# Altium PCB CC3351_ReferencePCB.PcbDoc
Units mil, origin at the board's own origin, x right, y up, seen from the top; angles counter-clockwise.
Board outline 433.07 x 433.07 mil, 4 copper layers (L01_TOP, L02_GND, L03_PWR, L04_BOTTOM), stack 29.496 mil thick; 15 components, 31 nets, 77 pads, 114 vias.
Unrouted connection lines stored in the file: 2.
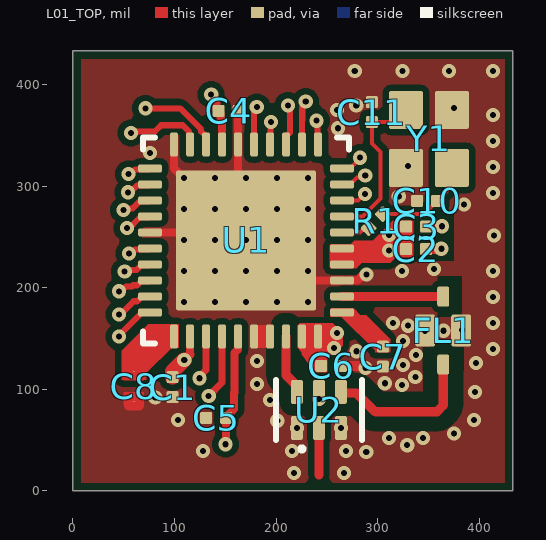
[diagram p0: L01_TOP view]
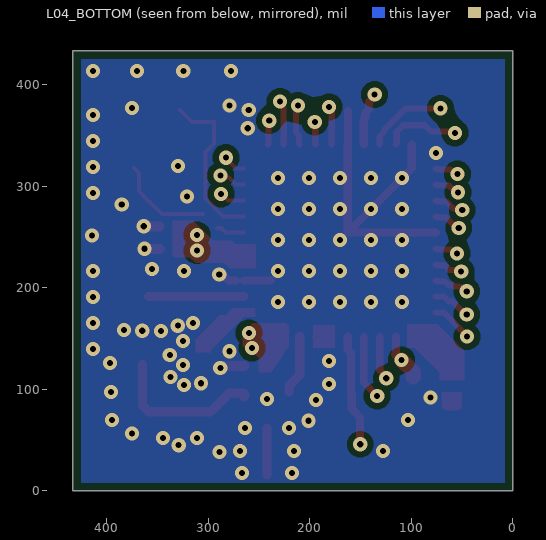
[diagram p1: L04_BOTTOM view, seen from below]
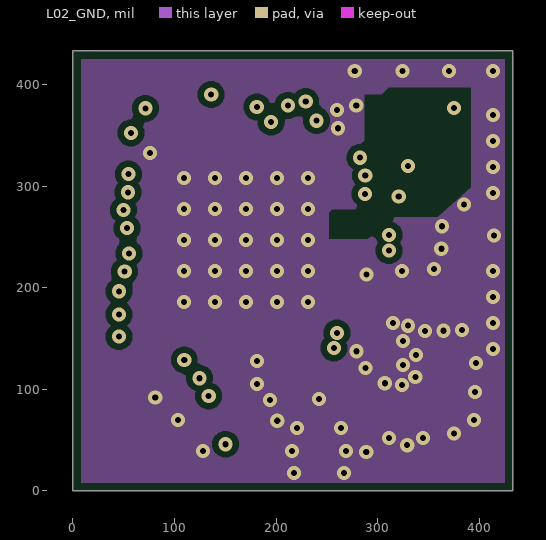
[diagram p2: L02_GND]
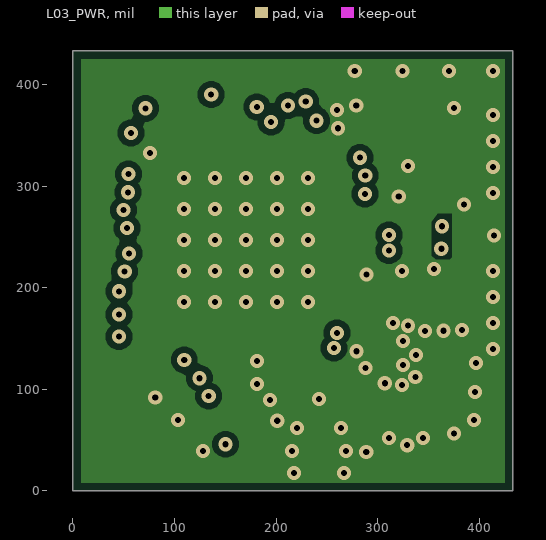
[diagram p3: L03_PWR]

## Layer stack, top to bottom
Top Solder: solder mask 1, Solder Resist, Dk 3.5
L01_TOP: signal copper 0.689
Dielectric1: prepreg 5.4819, IT-170GTTC, Dk 4
L02_GND: signal copper 1.2598
Dielectric 2: core 14.635, IT-170GTTC, Dk 4
L03_PWR: signal copper 1.2598
Dielectric 3: prepreg 5.4819, IT-170GTTC, Dk 4
L04_BOTTOM: signal copper 0.689
Bottom Solder: solder mask 1, Solder Resist, Dk 3.5

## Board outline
433.07,433.07 0,433.07 0,0 433.07,0

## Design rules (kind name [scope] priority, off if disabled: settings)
AcuteAngle [All] p1: minimum=4.50000000000000E+0001 checktracksonly=FALSE
AssemblyTestPointUsage [All] p1: valid=2
BoardOutlineClearance BoardOutlineClearance_MountingHoles [OnCopper and InComponentClass('Mounting Holes')] p1: gap=39.37 ignorepadtopadclearanceinfootprint=FALSE
BoardOutlineClearance BoardOutlineClearance_Poly [OnCopper and IsPoly] p2: gap=0 ignorepadtopadclearanceinfootprint=FALSE except(7.87: Poly-OutlineEdge)
BoardOutlineClearance [OnCopper and Not InComponentClass('Logo') and not InComponentClass('FiducialMark') and not InRegion(1000,500,4000,800) and not InPoly] p3: gap=9.84 ignorepadtopadclearanceinfootprint=FALSE
Clearance Clearance_RF [InNetClass('RF') vs InNet('GND')] p1: gap=6 ignorepadtopadclearanceinfootprint=TRUE except(7.87: Poly-Poly; 11: THPad-Poly Via-Poly; 11.25: SMDPad-Poly Fill-Poly; 15: Arc-Poly Track-Poly)
Clearance Clearance_Keepouts [((IsTrack Or IsArc) And Not InPoly) And IsFree and IsKeepOut vs ((IsTrack Or IsArc) And Not InPoly) And IsFree and IsKeepOut] p2: gap=0 ignorepadtopadclearanceinfootprint=FALSE
Clearance Clearance_Poly [InPolygon] p3: gap=6 ignorepadtopadclearanceinfootprint=TRUE except(5.5: Poly-Poly)
Clearance Clearance_FiducialMark [IsKeepOut and InComponentClass('FiducialMark') vs IsPad and InComponentClass('FiducialMark')] p4: gap=0 ignorepadtopadclearanceinfootprint=FALSE
Clearance [All] p5: gap=4 ignorepadtopadclearanceinfootprint=TRUE
ComponentClearance "Ignore Mod Component" [InComponent('CC1')] p1: gap=0 collisioncheckmode=3 verticalgap=0 showdistances=FALSE
ComponentClearance ComponentClearance_MountingHoles_FiducialMarks [InComponentClass('Mounting Holes') vs InComponentClass('FiducialMark')] p2: gap=50 collisioncheckmode=3 verticalgap=10 showdistances=FALSE
ComponentClearance ComponentClearance_Shunt [InComponentClass('Header') vs InComponentClass('Shunt')] p3: gap=0 collisioncheckmode=3 verticalgap=0 showdistances=FALSE
ComponentClearance ComponentClearance_Logo [InComponentClass('Logo')] p4: gap=30 collisioncheckmode=3 verticalgap=10 showdistances=FALSE
ComponentClearance ComponentClearance_ScrewToNut [(HasFootprint('NY PMS 440 0025 PH')) vs (HasFootprint('Keystone_1902C'))] p5: gap=5 collisioncheckmode=3 verticalgap=10 showdistances=FALSE
ComponentClearance ComponentClearance_MountingHoles [InComponentClass('Mounting Holes')] p6: gap=100 collisioncheckmode=3 verticalgap=100000 showdistances=FALSE
ComponentClearance ComponentClearance_SmallPassives [HasFootprint('0201*') or HasFootprint('0402*') or HasFootprint('0508') or HasFootprint('0603*') or HasFootprint('0612') or HasFootprint('0805*') or HasFootprint('0815*') or HasFootprint('0830*') or HasFootprint('1206*') or HasFootprint('1210*') or HasFootprint('1808*') or HasFootprint('1812*') or HasFootprint('1825*') or HasFootprint('2010*') or HasFootprint('2220*') or HasFootprint('2225*') or HasFootprint('2512*') or HasFootprint('2728*') or HasFootprint('3518*') vs HasFootprint('0201*') or HasFootprint('0402*') or HasFootprint('0508') or HasFootprint('0603*') or HasFootprint('0612') or HasFootprint('0805*') or HasFootprint('0815*') or HasFootprint('0830*') or HasFootprint('1206*') or HasFootprint('1210*') or HasFootprint('1808*') or HasFootprint('1812*') or HasFootprint('1825*') or HasFootprint('2010*') or HasFootprint('2220*') or HasFootprint('2225*') or HasFootprint('2512*') or HasFootprint('2728*') or HasFootprint('3518*')] p7: gap=8 collisioncheckmode=3 verticalgap=10 showdistances=FALSE
ComponentClearance ComponentClearance_THtoSMT [IsThruComponent vs IsSMTComponent] p8: gap=30 collisioncheckmode=3 verticalgap=30 showdistances=FALSE
ComponentClearance ComponentClearance_THtoTH [IsThruComponent vs IsThruComponent] p9: gap=20 collisioncheckmode=3 verticalgap=30 showdistances=FALSE
ComponentClearance [All] p10: gap=0 collisioncheckmode=3 verticalgap=10 showdistances=FALSE
DiffPairsRouting [All] p1: maxlimit=100 minlimit=10 mostfreqgap=10 toplayer_minwidth=15 toplayer_maxwidth=15 toplayer_prefwidth=15 midlayer1_minwidth=15 midlayer1_maxwidth=15 midlayer1_prefwidth=15 midlayer2_minwidth=15 midlayer2_maxwidth=15 midlayer2_prefwidth=15 bottomlayer_minwidth=15 bottomlayer_maxwidth=15 bottomlayer_prefwidth=15 maxuncoupledlength=1000
FabricationTestPointUsage TestPointUsage [All] p1: valid=2 allowmultiple=FALSE
FabricationTestpoint Testpoint [All] p1: side=3 testpointundercomponent=TRUE minsize=40 maxsize=100 preferedsize=60 minholesize=0 maxholesize=40 preferedholesize=32 testpointgrid=1 allowsidetop=TRUE allowsidebottom=TRUE usegrid=TRUE gridtolerance=0.01
FanoutControl Fanout_LCC [IsLCC] p1: bgadir=Out bgaviamode=Centered fanoutstyle=Auto fanoutdirection=Alternating viagrid=1 // Fanout_LCC (Default Rule)
FanoutControl Fanout_BGA [IsBGA] p2: bgadir=Out bgaviamode=Centered fanoutstyle=Auto fanoutdirection=Alternating viagrid=1 // Fanout_BGA (Default Rule)
FanoutControl Fanout_Default [All] p4: bgadir=Out bgaviamode=Centered fanoutstyle=Auto fanoutdirection=Alternating viagrid=1 // Fanout_Default (Default Rule)
FanoutControl Fanout_Small [(CompPinCount < 5)] p5: bgadir=Out bgaviamode=Centered fanoutstyle=Auto fanoutdirection=OutThenIn viagrid=1 // Fanout_Small (Default Rule)
HoleSize [All] p1: absolutevalues=TRUE maxlimit=251 minlimit=6 maxpercent=80.000 minpercent=20.000
HoleToHoleClearance [All] p1: gap=7 allowstackedmicrovias=TRUE
MinimumAnnularRing MinimumAnnularRing_ThermalPadVias [IsVia and InAnyComponent] p1: minimumring=3
MinimumAnnularRing [All] p2: minimumring=3
MinimumSolderMaskSliver MinimumSolderMaskSliver_Logo [InComponentClass('Logo') vs InComponentClass('Logo')] p1: minsoldermaskwidth=0.7
MinimumSolderMaskSliver [All] p2: minsoldermaskwidth=3.94
PlaneConnect [All] p1: planeconnectstyle=Direct reliefexpansion=10 reliefentries=4 reliefconductorwidth=10 reliefairgap=10
PolygonConnect [All] p1: connectstyle=Direct reliefconductorwidth=10 reliefentries=4 polygonreliefangle="90 Angle" airgapwidth=10
RoutingVias ThermalPadVias [IsVia and InAnyComponent] p1: holewidth=7.87 width=19.68 viastyle="Through Hole" minholewidth=6 minwidth=10 maxholewidth=12.99 maxwidth=23.62
RoutingVias [All] p2: holewidth=16 width=34 viastyle="Through Hole" minholewidth=6 minwidth=10 maxholewidth=40 maxwidth=65
SilkToBoardRegionClearance [Not ((IsComment or IsDesignator) And (Hide <> 'False')) and not InRegion(1000,500,4000,800)] p1:
SilkToSilkClearance SilkToSilkClearance_Pb-FreeLogo [(HasFootprint('Pb-Free_Overlay_Medium') OR HasFootprint('Pb-Free_Overlay_Small')) vs (HasFootprint('Pb-Free_Overlay_Medium') OR HasFootprint('Pb-Free_Overlay_Small'))] p1: silktosilkclearance=0
SilkToSilkClearance [All] p2: silktosilkclearance=3.94
SilkToSolderMaskClearance SilkToComponentPadClearance [(IsPad or IsFill or IsRegion) and InAnycomponent] p1: minsilkscreentomaskgap=5 clearancetoexposedcopper=TRUE
SilkToSolderMaskClearance "Silk to Solder Mask Opening" [All] p2: minsilkscreentomaskgap=3.94 clearancetoexposedcopper=FALSE
SolderMaskExpansion [All] p1: expansion=1.97 istentingtop=FALSE
UnRoutedNet [All] p1: checkbadconnections=TRUE
Width [All] p1: maxlimit=100 minlimit=4 preferedwidth=10 midlayer1_minwidth=6 midlayer2_minwidth=6 minimp=50.000000 maximp=50.000000 favimp=50.000000 checkconnectedcopper=TRUE
13 further rules are at their usual default settings.

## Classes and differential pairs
net class RF: NetFL1_3 RF_A

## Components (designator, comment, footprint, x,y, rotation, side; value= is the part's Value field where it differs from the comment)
C1 "GRM033C71A104KE14D" 0201#1 98.07,99.07 r270 top value=0.1uF
C2 "GRM033C71A104KE14D" 0201#1 340.78,238.05 r0 top value=0.1uF
C3 "GRM033C71A104KE14D" 0201#1 341,260.1 r0 top value=0.1uF
C4 "GRM033C71A104KE14D" 0201#2 150.07,374.07 r0 top value=0.1uF
C5 "GRM033C71A104KE14D" 0201#1 137.8,71.85 r180 top value=0.1uF
C6 "GRM033D70J105ME01D" FP-GRM033D70J105ME01D_0201-MFG#1 252.95,123.03 r180 top value=1µF
C7 "GRM033D70J105ME01D" FP-GRM033D70J105ME01D_0201-MFG#2 305.12,130.91 r90 top value=1µF
C8 "GRM155R70J105MA12D" 0402 60.07,94.07 r270 top value=1uF
C10 "GRM0335C1H6R8BA01D" 0201#1 345.47,285.43 r180 top value=6.8pF
C11 "GRM0335C1H6R8BA01D" 0201#1 294.29,375.98 r90 top value=6.8pF
FL1 "DEA162450BT-1295A1" FP-DEA162450BT-1295A1_SMT_FILTER_1MM60_0MM80-MFG 364.49,157.89 r270 top
R1 "RC0201FS-7D150RL" 0201#1 300.2,267.72 r45 top value=150
U1 "CC3351NG0ARSBR" RSB0040B-MFG 170.4,246.57 r180 top
U2 "DPX167125DT-8197B1" FP-DPX167125DT-8197B1_SMD6-MFG 242.13,79.72 r0 top
Y1 "TZ3877AAAO44" FP-TZ3877AAAO44_SMT4_2MM05_1MM65-MFG 350.39,346.46 r90 top

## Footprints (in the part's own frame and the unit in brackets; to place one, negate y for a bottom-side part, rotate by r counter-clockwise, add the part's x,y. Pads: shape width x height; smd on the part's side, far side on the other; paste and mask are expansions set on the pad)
0201#1 [mm] "Data from Kemet datasheet CC101_COM dated 7/28/11"
  rrect25% 0.3x0.3 smd mask+0.048: 1(-0.33,0) 2(0.17,0)
  body extent -0.31,-0.16 0.31,0.16, height 0.26
0201#2 [mm] "Data from Kemet datasheet CC101_COM dated 7/28/11"
  rrect25% 0.3x0.3 smd mask+0: 1(-0.17,0) 2(0.33,0)
  body extent -0.31,-0.16 0.31,0.16, height 0.26
0402 [mil] "0402 from SM-752 data"
  round 1 smd: 1(-23.62,0) 2(5.91,0)
  L01_TOP region: -14.76,9.84 -14.76,-9.84 -27.17,-9.84 -29.2,-9.44 -30.92,-8.29 -32.08,-6.56 -32.48,-4.53 -32.48,-4.53 -32.48,4.53 -32.08,6.56 -30.92,8.29 -29.2,9.44 -27.17,9.84 -27.17,9.84
  L01_TOP region: 14.76,-4.53 14.36,-6.56 13.21,-8.29 11.48,-9.44 9.45,-9.84 9.45,-9.84 -2.95,-9.84 -2.95,9.84 9.45,9.84 11.48,9.44 13.21,8.29 14.36,6.56 14.76,4.53 14.76,4.53
  body extent -22,-12 22,12, height 24
FP-DEA162450BT-1295A1_SMT_FILTER_1MM60_0MM80-MFG [mm]
  rrect33% 0.5x0.3 smd paste+0 mask+0.025: 1(-0.85,0) 3(0.85,0)
  rrect20% 0.8x0.5 smd paste+0 mask+0.025: 2(0,-0.45) 4(0,0.45)
  body extent -1.2,-0.8 1.2,0.8, height 0.25
FP-DPX167125DT-8197B1_SMD6-MFG [mm]
  rrect33% 0.3x0.6 smd paste+0 mask+0: 1(-0.55,-0.45) 2(0,-0.45) 3(0.55,-0.45) 4(0.55,0.45) 5(0,0.45) 6(-0.55,0.45)
  silkscreen extent -1.07,-1.03 1.07,0.75, body extent -0.95,-0.85 0.95,0.85, height 0.25
FP-GRM033D70J105ME01D_0201-MFG#1 [mm]
  rrect33% 0.3x0.3 smd paste+0 mask+0: 1(-0.282,0) 2(0.218,0)
  body extent -0.53,-0.3 0.53,0.3, height 0.25
FP-GRM033D70J105ME01D_0201-MFG#2 [mm]
  rrect33% 0.3x0.3 smd paste+0 mask+0: 1(-0.218,0) 2(0.282,0)
  body extent -0.53,-0.3 0.53,0.3, height 0.25
FP-TZ3877AAAO44_SMT4_2MM05_1MM65-MFG [mm]
  rrect12% 0.95x0.85 smd paste+0 mask+0: 1(-0.725,-0.575) 2(0.725,-0.575) 3(0.725,0.575) 4(-0.725,0.575)
  body extent -1.3,-1.1 1.3,1.1, height 0.25
RSB0040B-MFG [mm]
  rrect50% 0.6x0.2 smd paste+0 mask+0: 1(-2.4,1.8) 3(-2.4,1) 4(-2.4,0.6) 5(-2.4,0.2) 6(-2.4,-0.2) 7(-2.4,-0.6) 8(-2.4,-1) 9(-2.4,-1.4) 10(-2.4,-1.8) 21(2.4,-1.8) 22(2.4,-1.4) 23(2.4,-1) 24(2.4,-0.6) 25(2.4,-0.2) 26(2.4,0.2) 27(2.4,0.6) 28(2.4,1) 29(2.4,1.4) 30(2.4,1.8)
  rrect50% 0.6x0.2 smd: 2(-2.4,1.4)
  rrect50% 0.2x0.6 smd paste+0 mask+0: 11(-1.8,-2.4) 12(-1.4,-2.4) 13(-1,-2.4) 14(-0.6,-2.4) 15(-0.2,-2.4) 16(0.2,-2.4) 17(0.6,-2.4) 18(1,-2.4) 19(1.4,-2.4) 20(1.8,-2.4) 31(1.8,2.4) 32(1.4,2.4) 33(1,2.4) 34(0.6,2.4) 35(0.2,2.4) 36(-0.2,2.4) 37(-0.6,2.4) 39(-1.4,2.4) 40(-1.8,2.4)
  rrect50% 0.2x0.6 smd: 38(-1,2.4)
  rrect3% 3.5x3.5 smd paste-1000 mask+0: 41(0,0)
  silkscreen extent -2.58,-2.58 2.58,2.58, body extent -2.8,-2.8 2.8,2.8, height 0.25

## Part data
C1 C2 C3 C4 C5: library part CMP-0064969-1, "CAP, CERM, 0.1 uF, 10 V,+/- 10%, X7S, 0201", Cap_Case=0201, Manufacturer=MuRata, Supplier Part Number 1=490-14450-1-ND, Value1=Unknown, Value2=10V, ValueDisplayed=0.1uF
C6 C7: library part CMP-0095016-1, "Chip Multilayer Ceramic Capacitors for General Purpose, 0201, 1.0uF, X7T, +22%/-33%, 20%, 6.3V", Manufacturer=Murata, Operating Temperature Range="-55°C to +125°C", TempCo=+22%/-33%, Tolerance_%=20%, ValueDisplayed=1.0uF
C8: library part CMP-0006624-2, "CAP, CERM, 1 uF, 6.3 V, +/- 20%, X7R, 0402", Cap_Case=0402, Manufacturer=MuRata, Supplier Part Number 1=490-9665-1-ND, TempCo=X7R, Tolerance_%=20%, Value1=Unknown, Value2=6.3V, ValueDisplayed=1uF
C10 C11: library part CMP-0009669-4, "CAP, CERM, 6.8 pF, 50 V, +/- 2%, C0G/NP0, 0201", Cap_Case=0201, Manufacturer=MuRata, Supplier Part Number 1=GRM0335C1H6R8BA01D-ND, TempCo=C0G/NP0, Tolerance_%=2%, Value1=Unknown, Value2=50V, ValueDisplayed=6.8pF
FL1: library part CMP-0091509-1, "2.45GHz Center Frequency Band Pass RF Filter (Radio Frequency) 100MHz Bandwidth 1.8dB 0603 (1608 Metric), 3 PC Pad", Digikey Part Number=445-175610-1-ND, Frequency_Fixed=2.45GHz, Manufacturer=TDK, Mouser Part Number=810-DEA162450BT1295A, Operating Temperature Range="-40°C to +85°C"
R1: library part CMP-0028078-1, "RES, 150, 1%, 0.05 W, 0201", Manufacturer="Yageo America", Power_W=50mW, Supplier Part Number 1=603-RC0201FS-7D150RL, TempCo="200 ppm/C", Tolerance_%=1%, Value2=0.05W, Value_Code=150R, ValueDisplayed=150
U1: library part CMP-0094602-1, Manufacturer="Texas Instruments", Operating Temperature Range=to, Part Number=CC3301NG0ARSBR
U2: library part CMP-0091972-1, "Multilayer Diplexer For 2.4-2.5GHz W-LAN & Bluetooth / 5-7GHz W-LAN", Manufacturer=TDK, Operating Temperature Range="-40°C to +85°C"
Y1: library part CMP-0094297-1, "Crystal Unit SMD 2.0x1.6 40.0MHz", Frequency Stability=-16/+18ppm, Frequency Tolerance=5ppm, Frequency_Fixed=40MHz, Load Capacitance=7pF, Manufacturer="TAI-SAW TECHNOLOGY", Operating Temperature Range="-40°C to +105°C"

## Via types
v1: diameter 14, hole 6, L01_TOP to L04_BOTTOM, tented both sides, 78 vias
v2: diameter 14, hole 6, L01_TOP to L04_BOTTOM, 34 vias
v3: diameter 14, hole 6, L01_TOP to L04_BOTTOM, tented top, 2 vias

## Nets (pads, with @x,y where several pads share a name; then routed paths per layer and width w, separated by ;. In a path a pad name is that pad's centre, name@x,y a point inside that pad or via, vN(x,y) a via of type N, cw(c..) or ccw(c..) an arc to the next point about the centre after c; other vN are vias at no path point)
1V8: C1.1 C2.1 C3.1 C4.1 C5.1 U1.4 U1.5 U1.17 U1.32 U1.35 | length 215.9
  L01_TOP w7.8: 115.28,134.45 U1.32
  L01_TOP w8: v1@137.08,389.06 ccw(c136.07,389.06) v1(136.07,390.07) 136.07,388.45 141.47,383.05 141.47,375.98 C4.1 145.28,372.17 145.28,366.87 146.78,365.37 U1.17 ; v1(150.26,45.9) 150.52,46.17 150.52,71.59 C5.1 ; C5.1@153.64,75.64 158.57,80.57 158.57,96.25 159.22,96.9 159.22,135.99 162.53,139.3 U1.35
  L01_TOP w9: 104.42,123.59 115.28,134.45
  L01_TOP w15: C1.1 98.07,117.45 v2(109.54,128.92)
  other v2: 311.02,236.59 311.02,251.97
3V3: C6.2 U1.39 U1.40
  other v2: 256.89,140.75 259.84,155.51
ANT_SEL: U1.15 | length 38.1
  L01_TOP w6: U1.15 178.28,373.11 181,375.84 v2(181,378)
COEX_GRA: U1.10 | length 22.4
  L01_TOP w4: U1.10 272.77,317.44 282.48,327.15 v2(282.48,327.98)
COEX_PRI: U1.9 | length 26.5
  L01_TOP w4: U1.9 272.77,301.69 279.67,308.6 285.83,308.6 v2(287.74,310.51)
COEX_REQ: U1.8 | length 25.2
  L01_TOP w4: U1.8 280.44,285.94 286.82,292.32 v2(287.4,292.32)
DIG_LDO_OUT: C8.1 U1.31
GND: C1.2 C2.2 C3.2 C4.2 C5.2 C6.1 C7.1 C8.2 C10.2 C11.2 FL1.2 FL1.4 U1.3 U1.16 U1.20 U1.25 U1.36 U1.37 U1.41 U2.1 U2.3 U2.5 Y1.2 Y1.4 | length 420.9
  L01_TOP w7: U1.37@193.59,152.52 U1.37
  L01_TOP w8: U1.25 U1.41@162.53,254.45 ; U1.20 99.54,317.44 U1.41@162.53,254.45 ; C4.2@162.47,373.91 162.47,341.12 U1.16 U1.41@162.53,254.45 ; U1.41@238.07,207.07 238.2,207.2 U1.3 ; U1.3@272.7,207.26 279.92,207.26 284.51,211.85 286.23,211.85 287.38,213 v1(289,213)
  L01_TOP w10: C6.1 C6.1@264.96,123.03 ; C6.1@264.98,123.02 284.9,123.02 286.92,121 v1(288,121) ; C2.2 347.6,238.18 362.51,238.18 v2(362.64,238.31) ; C3.2 347.91,260.32 363.14,260.32 v2(363.36,260.55)
  other v1: 217.52,17.72 266.73,17.72 288.75,38.39 127.95,39.37 215.55,39.37 268.7,39.37 329,45 375,56.6 220.47,62.01 263.78,62.01 201.07,69.07 394.68,69.88 193.9,89.57 242.13,90.55 81.07,92.07 395.67,97.44 323.82,104.33 181.1,105.31 307,106 337,112 324.8,124.02 396.65,125.98 181.1,127.81 337.7,133.86 278.99,137.44 413.39,139.76 324.8,147.64 346.46,157.48 364.8,157.64 382.87,158.46 329.8,162.64 314.96,165.35 413.39,165.35 109.25,186.02 139.76,186.02 170.28,186.02 200.79,186.02 231.3,186.02 413.39,190.94 109.25,216.54 139.76,216.54 170.28,216.54 200.79,216.54 231.3,216.54 323.82,216.54 413.39,216.54 355.31,218.5 109.25,247.05 139.76,247.05 170.28,247.05 200.79,247.05 231.3,247.05 414.39,251.31 109.25,277.56 139.76,277.56 170.28,277.56 200.79,277.56 231.3,277.56 385,282 320.72,289.88 413.39,293.31 109.25,308.07 139.76,308.07 170.28,308.07 200.79,308.07 231.3,308.07 413.39,318.9 329.72,319.88 413.39,344.49 375,376.97 277.39,413.31 324.39,413.31 370.08,413.39
  other v2: 311.02,52.07 344.49,52.07 103.35,69.88 75.79,332.68 261,357 260,375 278.9,379.44
  other v3: 413.39,370.08 413.39,413.39
HFXT_M: C11.1 U1.7 Y1.3 | length 162.4
  L01_TOP w4: U1.7 285.25,270.19 302.78,287.73 302.78,333.51 294.29,342 C11.1 315.75,362.99 Y1.3
HFXT_P: R1.1 U1.6 | length 27.8
  L01_TOP w4: U1.6 282.7,254.45 286.79,258.53 R1.1
HOST_IRQ_BLE: U1.30 | length 41.1
  L01_TOP w6: v2(45.27,151.9) 45.27,152.93 68.04,175.71 U1.30
HOST_IRQ_WL: U1.29 | length 37.9
  L01_TOP w6: v2(45.45,173.52) 46.58,173.52 59.7,186.64 63.23,186.64 68.04,191.45 U1.29
LOGGER: U1.28 | length 34.9
  L01_TOP w6: v2(45.45,196.43) 47.61,196.43 52.49,201.31 58.03,201.31 59.11,202.39 63.23,202.39 67.1,206.26 74.98,206.26 U1.28
NetC10_1: C10.1 R1.2 Y1.1 | length 97.4
  L01_TOP w4: R1.2 345.48,272.45 C10.1 368.03,295 368.03,312.91 Y1.1
NetFL1_3: FL1.3 U2.4 | length 153.9
  L01_TOP w9.15: U2.4@265.11,92.48 263.78,93.81 263.78,95.11 265.11,96.44 278.9,96.44 297.15,78.19 ; 298,78 358.3,78 364.49,84.19 FL1.3
PA_LDO_OUT: C7.2 U1.1
RESET: U1.33 | length 43.8
  L01_TOP w7: v2(124.7,110.87) 124.7,112.76 131.03,119.1 U1.33
RF_A: U1.38 U2.6 | length 59.1
  L01_TOP w9.15: U1.38 209.77,114.05 220.47,103.35 U2.6
SDIO_CLK: U1.19 | length 75.9
  L01_TOP w6: v1(57.09,352.36) 58.62,353.89 80.79,353.89 86.77,359.87 108.1,359.87 114.35,353.63 114.35,342 U1.19
SDIO_CMD: U1.18 | length 80.3
  L01_TOP w6: v2(71.32,376.57) 105.54,376.57 126.22,355.89 126.22,353.74 131.03,348.93 U1.18
SDIO_D0: U1.24 | length 27.4
  L01_TOP w6: v2(53.31,258.73) 55.48,258.73 66,269.26 74.98,269.26 U1.24
SDIO_D1: U1.23 | length 30
  L01_TOP w6: v2(49.85,276.39) 51.38,277.92 58.61,277.92 65.69,285 74.98,285 U1.23
SDIO_D2: U1.22 | length 25
  L01_TOP w6: v2(54.13,293.88) 56.3,293.88 63.18,300.75 74.98,300.75 U1.22
SDIO_D3: U1.21 | length 23.6
  L01_TOP w6: v2(54.66,311.87) 56.83,311.87 61.46,316.5 74.98,316.5 U1.21
SLOW_CLOCK_IN: U1.34 | length 64
  L01_TOP w7: v2(133.62,93.54) 146.78,106.7 U1.34
SWCLK: U1.26 | length 22.9
  L01_TOP w6: v2(55.1,233.73) 57.27,233.73 61.3,237.76 74.98,237.76 U1.26
SWDIO: U1.27 | length 27.8
  L01_TOP w6: v2(50.92,216.08) 52.45,217.61 62.7,217.61 67.1,222.01 74.98,222.01 U1.27
UART_CTS: U1.12 | length 43.7
  L01_TOP w6: U1.12 225.52,364.22 225.75,364.45 225.75,377.61 229.2,381.06 v2(229.2,383.22)
UART_RTS: U1.11 | length 23.9
  L01_TOP w6: v2(239.82,364.4) 240.55,363.68 240.55,341.78 U1.11
UART_RX: U1.13 | length 40.7
  L01_TOP w6: U1.13 210.71,342 210.71,349.87 213.47,352.63 213.47,375.41 211.6,377.28 v2(211.6,379.44)
UART_TX: U1.14 | length 22.3
  L01_TOP w6: U1.14 194.51,341.55 194.51,362.51 v2(195,363)
pads on no net: FL1.1 U1.2 U2.2
copper on no net: | length 139.8
  L01_TOP w9.15: 242.13,16 242.13,62.01 ; 264.89,191.45 358.72,191.45

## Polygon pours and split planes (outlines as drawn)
GND on L03_PWR "L03_PWR_GND_P009" (solid, remove dead copper, pour order 9): 433.07,0 433.07,433.07 0,433.07 0,0
GND on L02_GND "L02_GND_GND_P001" (solid, remove dead copper, pour order 1): 433.07,433.07 0,433.07 0,0 433.07,0
GND on L01_TOP "L01_TOP_GND_P003" (solid, remove dead copper, pour order 3): 433.07,433.07 433.07,0 0,0 0,433.07
GND on L04_BOTTOM "L04_BOTTOM_GND_P007" (solid, remove dead copper, pour order 7): 433.07,0 433.07,433.07 0,433.07 0,0

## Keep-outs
Keep-Out Layer:
  text ".Layer_Name" at 611.35,-825.25 h60

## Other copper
L01_TOP:
  rectangle net GND: 175.2,140.75 196.85,163.39
  pour cut-out: 358.72,211.99 358.72,170.82 382.99,170.82 382.99,211.99
  pour cut-out: 344,117.86 385.17,117.86 385.17,142.14 344,142.14
  region net 3V3: 256.89,133.86 253.37,133.86 250.35,130.84 250.35,116.93 237.79,116.85 225.35,134.58 225.35,136.59 220.65,141.29 220.65,162.44 223.26,165.05 255.89,165.05 265.75,155.19 265.75,142.72
  region net 1V8: 253.9,219.07 252.9,220.07 252.9,241.57 253.9,242.57 273.4,242.57 276.9,246.07 295.14,246.07 314.81,265.75 334.9,265.75 334.9,231.57 333.4,230.07 317.9,230.07 312.4,224.57 284.4,224.57 278.9,219.07
  region net PA_LDO_OUT: 276.4,179.57 254.27,179.57 253.4,178.71 253.4,171.41 264.27,171.41 297.4,138.28 297.4,136.42 312.26,136.42 312.4,136.57 312.4,149.45 288.75,173.1 282.88,173.1
  pour cut-out: 342.52,226.38 342.52,272.64 375,272.64 375,226.38
  region net DIG_LDO_OUT: 104.07,141.07 104.07,144.68 104.07,164.07 74.07,164.07 48.07,138.07 48.07,109.25 72.07,109.25 72.07,116.07 97.07,141.07
  text ".Layer_Name" at 611.35,-825.25 h60
L02_GND:
  pour cut-out: 391.73,396.65 391.73,298.75 358.92,269.88 312.2,269.88 290.35,248.03 252.23,248.03 252.23,273.71 255.09,276.57 284.92,276.57 298.02,289.68 298.02,330.91 287.4,341.54 287.4,389.76 303.96,389.76 310.85,396.66
L03_PWR:
  pour cut-out: 353.18,265.05 359.15,272.64 373,272.63 373,229.83 371.03,227.86 356.88,227.86 353.18,231.55
L04_BOTTOM:
  text ".Layer_Name" at 611.35,-825.25 h60

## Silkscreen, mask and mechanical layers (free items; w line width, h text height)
Top Overlay:
  text ".Layer_Name" at 611.35,-825.25 h60
Bottom Overlay:
  text ".Layer_Name" at 611.35,-825.25 h60
Top Paste:
  region: 425.04,8.03 425.04,236 401.42,236 401.42,8.03
  region: 223,31.65 8.03,31.65 8.03,8.03 223,8.03
  region: 425.04,31.68 261,31.68 261,8.03 425.04,8.03
  region: 31.65,8.03 31.65,147.64 8.03,147.64 8.03,8.03
  region: 31.65,175.2 31.65,425.04 8.03,425.04 8.03,175.2
  region: 425.04,425.04 143.58,425.04 143.58,401.42 425.04,401.42
  region: 112.2,425.04 8.03,425.04 8.03,401.42 112.2,401.42
  region: 425.04,266.58 425.04,425.04 401.42,425.04 401.42,266.58
  text ".Layer_Name" at 611.35,-825.25 h60
Bottom Paste:
  text ".Layer_Name" at 611.35,-825.25 h60
Top Solder:
  region: 425.04,8.03 425.04,236 401.42,236 401.42,8.03
  region: 425.04,266.58 425.04,425.04 401.42,425.04 401.42,266.58
  region: 31.65,8.03 31.65,147.64 8.03,147.64 8.03,8.03
  region: 112.2,425.04 8.03,425.04 8.03,401.42 112.2,401.42
  region: 425.04,31.65 261,31.65 261,8.03 425.04,8.03
  region: 223,31.65 8.03,31.65 8.03,8.03 223,8.03
  region: 425.04,425.04 143.58,425.04 143.58,401.42 425.04,401.42
  region: 31.65,175.04 31.65,425.04 8.03,425.04 8.03,175.04
  text ".Layer_Name" at 611.35,-825.25 h60
  text ".Layer_Name" at 611.35,-825.25 h60
Bottom Solder:
  text ".Layer_Name" at 611.35,-825.25 h60
Drill Guide:
  text ".Layer_Name" at 611.35,-825.25 h60
M1 Board Outline:
  the board outline again, w10
  text ".Layer_Name" at 611.35,-825.25 h60
M2 Board Dimensions:
  rectangle: 34.35,-241.76 159.35,-116.76
  rectangle: 159.35,-366.76 534.35,-241.76
  lines w7: 34.35,-241.76 1034.35,-241.76 ; 159.35,-366.76 159.35,-116.76 ; 284.35,-366.76 284.35,-116.76 ; 534.35,-366.76 534.35,-116.76 ; 784.35,-366.76 784.35,-116.76 ; 34.35,-366.76 1034.35,-366.76 1034.35,-116.76 34.35,-116.76 34.35,-366.76
  text ".Layer_Name" at 611.35,-825.25 h60
M3 3D STEP Top:
  text ".Layer_Name" at 611.35,-825.25 h60
M4 3D STEP Bottom:
  text ".Layer_Name" at 611.35,-825.25 h60
M5 Assembly Top:
  lines w10: -257.65,-896.93 6342.35,-896.93 ; -257.65,-693.59 6344.35,-693.59 ; -257.65,-490.26 -257.65,-1100.26 3747.35,-1100.26 6344.35,-1100.26 6344.35,-490.26 -257.15,-490.26 -257.15,-1100.26 1318.35,-1100.26 ; 2207.35,-1100.26 2207.35,-490.26 ; 3474.35,-693.59 3474.35,-490.26 ; 4314.35,-693.59 4314.35,-490.26 ; 4936.35,-1106.76 4936.35,-903.93
  text "COMPONENTS MARKED 'DNP' SHOULD NOT BE POPULATED." at 1187.85,-285.26 h60
  text "ASSEMBLY VARIANT:" at 1187.35,-400.76 h60
  text ".VariantName" at 2223.35,-400.76 h60
  text "PCB VIEWED FROM TOP SIDE" at -194.15,-622.43 h60
  text "BOARD #:" at 2282.35,-622.43 h60
  text ".PRJ_Number" at 2827.85,-622.43 h60
  text "REV:" at 3672.35,-622.43 h60
  text ".PCB_Rev" at 3963.85,-622.43 h60
  text "SVN REV:" at 4510.35,-622.43 h60
  text ".VersionControl_RevNumber" at 5016.35,-622.43 h60
  text "TID #:" at 2282.35,-825.76 h60
  text ".TID" at 2827.85,-825.76 h60
  text "PLOT NAME =" at -194.15,-1031.09 h60
  text ".plot_File_Name" at 611.35,-1031.09 h60
  text "GENERATED    :" at 2284.35,-1031.09 h60
  text ".Print_Date" at 3153.85,-1031.09 h60
  text ".Print_Time" at 3882.85,-1031.09 h60
  text "TEXAS INSTRUMENTS" at 5147.35,-1031.09 h60
M6 Assembly Bottom:
  lines w10: -258.15,-694.09 6343.85,-694.09 ; -256.15,-897.43 6343.85,-897.43 ; 1149.85,-1107.26 1149.85,-904.43 ; 1771.85,-694.09 1771.85,-490.76 ; 2611.85,-694.09 2611.85,-490.76 ; 3878.85,-1100.76 3878.85,-490.76 ; 4767.85,-1100.76 6343.35,-1100.76 6343.35,-490.76 -258.15,-490.76 -258.15,-1100.76 2338.85,-1100.76 6343.85,-1100.76 6343.85,-490.76
  text "COMPONENTS MARKED 'DNP' SHOULD NOT BE POPULATED." at 6136.35,-284.76 h60
  text ".VariantName" at 5092.35,-400.76 h60
  text "ASSEMBLY VARIANT:" at 6131.35,-400.76 h60
  text ".VersionControl_RevNumber" at 1069.85,-622.93 h60
  text "SVN REV:" at 1575.85,-622.93 h60
  text ".PCB_Rev" at 2122.35,-622.93 h60
  text "REV:" at 2413.85,-622.93 h60
  text ".PRJ_Number" at 3258.35,-622.93 h60
  text "BOARD #:" at 3803.85,-622.93 h60
  text "PCB VIEWED FROM BOTTOM SIDE" at 6280.35,-622.93 h60
  text ".TID" at 3258.35,-826.26 h60
  text "TID #:" at 3803.85,-826.26 h60
  text "TEXAS INSTRUMENTS" at 938.85,-1031.59 h60
  text ".Print_Time" at 2203.35,-1031.59 h60
  text ".Print_Date" at 2932.35,-1031.59 h60
  text "GENERATED    :" at 3801.85,-1031.59 h60
  text ".plot_File_Name" at 5474.85,-1031.59 h60
  text "PLOT NAME =" at 6280.35,-1031.59 h60
M9 Title Sheet:
  drawing of 57 lines, arcs and shapes, not listed
  text "1" at 774.18,8069.74 h70
  text "2" at 3269.85,8069.74 h70
  text "3" at 5759.19,8069.74 h70
  text "4" at 8265.86,8069.74 h70
  text "5" at 10764.85,8069.74 h70
  text "6" at 13269.85,8069.74 h70
  text "A" at -382.15,6926.74 h70
  text "A" at 14417.85,6926.74 h70
  text "B" at -382.15,4546.74 h70
  text "B" at 14417.85,4546.74 h70
  text "C" at -382.15,2171.74 h70
  text "C" at 14417.85,2171.74 h70
  text "PROJECT TITLE:" at 11377.85,310.74 h45
  text ".PRJ_Title" at 11427.85,177.41 h70
  text "DESIGNED FOR:" at 11377.85,9.74 h45
  text ".PRJ_Customer" at 11427.85,-130.26 h70
  text "D" at -382.15,-198.26 h70
  text "D" at 14417.85,-198.26 h70
  text "FILE NAME:" at 11377.85,-290.26 h45
  text ".PCB_File_Name_No_Path" at 11427.85,-410.26 h70
  text "Texas Instruments (TI) and/or its licensors do not warrant the accuracy or completeness of this specification" at 6408.35,-572.1 h45
  text "ENGINEER:" at 11377.85,-580.26 h45
  text "LAYOUT BY:" at 12882.85,-580.26 h45
  text "or any information contained therein. TI and/or its licensors do not warrant that this design will meet" at 6363.36,-684.76 h45
  text ".PRJ_Engineer" at 11427.85,-735.25 h70
  text ".PCB_Layout" at 12933.35,-735.25 h70
  text "the specifications, will be suitable for your application or fit for any particular purpose, or will operate in" at 6363.36,-797.43 h45
  text ".Layer_Name" at 611.35,-825.25 h60
  text "ALTIUM DESIGNER VERSION:" at 12882.85,-890.26 h45
  text "an implementation. TI and/or its licensors do not warrant that the design is production worthy. You should" at 6363.36,-910.09 h45
  text "completely validate and test your design implementation to confirm the system functionality for your application." at 6408.35,-1022.76 h45
  text ".print_Scale" at 11427.85,-1023.59 h70
  text ".Application_BuildNumber" at 12933.35,-1023.59 h70
  text "1" at 774.18,-1230.26 h70
  text "2" at 3269.85,-1230.26 h70
  text "3" at 5759.19,-1230.26 h70
  text "4" at 8265.86,-1230.26 h70
  text "5" at 10764.85,-1230.26 h70
  text "6" at 13269.85,-1230.26 h70
M10 Fab Notes:
  drawing of 195 lines, arcs and shapes, not listed
  text "DESIGN INFORMATION" at 12416.37,6389.42 h60
  text "MIN. TRACK WIDTH:" at 11771.81,6257.29 h60
  text "4" at 12868.05,6257.29 h60
  text "MIL" at 13022.81,6257.29 h60
  text "4" at 12868.06,6146.89 h60
  text "MIN. CLEARANCE:" at 11771.81,6133.16 h60
  text "MIL" at 13022.81,6133.16 h60
  text "MIN. VIA PAD SIZE:" at 11771.81,6009.04 h60
  text "10" at 12838.06,6009.04 h60
  text "MIL" at 13022.81,6009.04 h60
  text "0.05mm (2MIL)" at 12466.81,5879.14 h60
  text "MINIMUM ANNULAR RING" at 11442.58,5870.92 h60
  text "EXTERNAL" at 13174.81,5870.92 h60
  text "PER" at 11642.58,5760.79 h60
  text "IPC-D-275 CLASS 2 LEVEL C" at 11862.58,5760.79 h60
  text "MIL, HOLES" at 13350.81,5660.31 h60
  text "+/-" at 12958.35,5651.72 h60
  text "+/-" at 13812.35,5651.72 h60
  text "REGISTRATION TOLERANCES:" at 11442.58,5650.66 h60
  text "METAL" at 12642.35,5650.66 h60
  text "5" at 13218.55,5650.66 h60
  text "3" at 14051.55,5650.66 h60
  text "MIL" at 14167.81,5650.66 h60
  text "HOLE SIZE TOLERANCE (UNLESS OTHERWISE SPECIFIED):" at 11442.58,5552.34 h60
  text "+/-" at 13812.35,5549.47 h60
  text "3" at 14051.55,5548.41 h60
  text "MIL" at 14167.81,5548.41 h60
  text "MATERIAL:" at 11367.81,5410.76 h60
  text "FR-4 High Tg" at 12354.25,5282.24 h60
  text "X" at 13095.43,5275.83 h60
  text "IT-170GTTC" at 13704.68,5273.86 h39.37
  text "FR-408" at 11788.81,5269.73 h60
  text "OTHER" at 13276.81,5269.73 h60
  text "0.8mm" at 13758.81,5130.16 h39.37
  text "62 MIL (1.6mm) +/-10%" at 12108.91,5126.7 h60
  text "X" at 13268.66,5126.23 h60
  text "THICKNESS:" at 11442.58,5118.48 h60
  text "OTHER" at 13393.81,5118.48 h60
  text "TOLERANCE:" at 11442.58,4980.16 h60
  text "X" at 12290.81,4980.16 h60
  text "ANSI IPC-6012 TYPE 3 CLASS 2" at 12468.82,4980.16 h60
  text "OTHER +/-" at 12468.81,4835.97 h60
  text "BOW & TWIST:" at 11442.58,4690.79 h60
  text "X" at 12290.81,4690.79 h60
  text "ANSI IPC-6012 TYPE 3 CLASS 2" at 12468.82,4690.79 h60
  text "OTHER +/-" at 12468.81,4544.09 h60
  text "DRILLING:" at 11367.81,4413.47 h60
  text "NC_DRILL FILES" at 13128.81,4308.28 h60
  text "REFERENCE:" at 11442.58,4304.34 h60
  text "X" at 12099.81,4304.25 h60
  text "AS SHOWN" at 12277.81,4304.34 h60
  text "X" at 13000.81,4304.34 h60
  text "OTHER" at 13426.81,4162.09 h60
  text "PTH COPPER THICKNESS:" at 11442.25,4158.56 h60
  text "X" at 12581.49,4158.56 h60
  text "20-30 um" at 12709.48,4158.56 h60
  text "BOARD FINISH:" at 11367.81,4010.97 h60
  text "SILKSCREEN:" at 11523.03,3900.84 h60
  text "X" at 12480.81,3900.84 h60
  text "TOP" at 12597.81,3900.84 h60
  text "X" at 12990.81,3900.84 h60
  text "BOTTOM" at 13108.81,3900.84 h60
  text "SILKSCREEN COLOR:" at 11523.03,3745.65 h60
  text "X" at 12479.81,3745.65 h60
  text "WHITE" at 12597.81,3745.65 h60
  text "OTHER" at 13108.81,3745.65 h60
  text "X" at 12610.81,3602.2 h60
  text "GREEN" at 12728.81,3602.2 h60
  text "OTHER" at 13346.81,3602.2 h60
  text "SOLDER RESIST COLOR:" at 11523.03,3595.34 h60
  text "X" at 12610.81,3447.95 h60
  text "MATTE" at 12728.81,3447.95 h60
  text "SEMI-GLOSS" at 13346.35,3447.31 h60
  text "IMMERSION GOLD (ENIG)" at 12428.81,3275.18 h60
  text "ENEPIG" at 13766.35,3267.96 h60
  text "SURFACE FINISH:" at 11367.81,3266.96 h60
  text "X" at 12250.81,3266.96 h60
  text "IMM. TIN/SILVER OR EQUIV" at 11697.35,3129.64 h60
  text "OTHER" at 13128.81,3125.71 h60
  text "ARRAY/PANEL:" at 11367.81,2970.33 h60
  text "CUT AND TRIM PER M1 BOARD OUTLINE" at 12428.81,2962.11 h60
  text "N.C. ROUTE" at 12428.81,2826.14 h60
  text "V. SCORE" at 13294.81,2826.14 h60
  text "X" at 12249.95,2819.14 h60
  text "CERTIFICATION:" at 11367.81,2697.01 h60
  text "MATERIALS AND WORKMANSHIP FOR ALL PCBS" at 12092.81,2697.01 h60
  text "TO MEET OR EXCEED THE REQUIREMENTS OF:" at 12092.81,2602.95 h60
  text "X" at 11730.32,2474.32 h60
  text "ANSI IPC-A-600F CLASS ->" at 11858.31,2474.32 h60
  text "X" at 13506.32,2474.32 h60
  text "2" at 13616.31,2474.32 h60
  text "1" at 13301.31,2472.82 h60
  text "3" at 13970.31,2472.82 h60
  text "X" at 12542.32,2326.64 h60
  text "RoHS" at 12670.31,2326.64 h60
  text "OTHER" at 13314.71,2326.64 h60
  text "PER ORDER" at 13711.77,2326.64 h60
  text "ALL BOARDS MUST MEET OR EXCEED UL94-V0 REQUIREMENTS." at 11395.35,2172.81 h60
  text "IMPEDANCE TABLE:" at -142.25,2096.59 h60
  text "PCB MUST BEAR THE UL94V-0 UL REGISTERED MATERIAL ID NUMBER" at 11395.35,2056.75 h60
  text "50 OHM CPWG" at 1114.75,1948.54 h50
  text "LAYER" at -80.25,1900.59 h60
  text "(COATED)" at 1240.63,1889.54 h40
  text "ADDITIONAL REQUIREMENTS:" at 11367.81,1887.32 h60
  text "(TW / AG)" at 1222.75,1837.64 h40
  text "MICROSECTION:" at 11442.58,1780.19 h60
  text "YES" at 12348.31,1780.19 h60
  text "9.15/15 MIL" at 1028.63,1687.54 h55
  text "L01_TOP" at -62.25,1680.59 h60
  text "REQUIRED" at 13209.81,1635.86 h60
  text "BARE BOARD ELEC. TEST:" at 11442.58,1633.01 h60
  text "NONE" at 12748.31,1633.01 h60
  text "X" at 13091.81,1633.01 h60
  text "PER ORDER" at 13801.81,1633.01 h60
  text "XX MIL VIAS REQUIRE NON-CONDUCTIVE FILL AND PLANARIZE" at 11610.73,1428.06 h59
  text "14 MIL VIAS REQUIRE CONDUCTIVE FILL AND PLANARIZE" at 11618.73,1324.08 h60
  text "X" at 11500.98,1318.76 h60
  text "TOLERANCE : +/-10%" at -125.17,1262.24 h60
  text "OUTER 9.15 & 11.81 MIL TRACES REQUIRE 50OHM SINGLE-ENDED IMPEDANCE" at 11610.24,1172.24 h50
  text "X" at 11504.91,1152.42 h60
  text "LAYER 2 & 3 (INNER LAYERS) XX MIL WIDE, XX MIL SPACE / TRACES REQUIRE 100 OHM DIFFERENTIAL IMPEDANCE" at 11609.74,924.99 h60
  text ".Layer_Name" at 611.35,-825.25 h60
M11 Gerber Information:
  lines w10: -257.65,-896.93 6342.35,-896.93 ; -257.65,-693.59 6344.35,-693.59 ; -257.65,-490.26 -257.65,-1100.26 3747.35,-1100.26 6344.35,-1100.26 6344.35,-490.26 -257.15,-490.26 -257.15,-1100.26 1318.35,-1100.26 ; 2207.35,-1100.26 2207.35,-490.26 ; 3474.35,-693.59 3474.35,-490.26 ; 4314.35,-693.59 4314.35,-490.26 ; 4936.35,-1106.76 4936.35,-903.93
  text "ALL ARTWORK VIEWED FROM TOP SIDE" at -194.15,-622.43 h60
  text "BOARD #:" at 2282.35,-622.43 h60
  text ".PRJ_Number" at 2827.85,-622.43 h60
  text "REV:" at 3672.35,-622.43 h60
  text ".PCB_Rev" at 3963.85,-622.43 h60
  text "SVN REV:" at 4510.35,-622.43 h60
  text ".VersionControl_RevNumber" at 5016.35,-622.43 h60
  text "LAYER NAME =" at -194.15,-825.25 h60
  text "TID #:" at 2282.35,-825.76 h60
  text ".TID" at 2827.85,-825.76 h60
  text "PLOT NAME =" at -194.15,-1031.09 h60
  text ".plot_File_Name" at 611.35,-1031.09 h60
  text "GENERATED    :" at 2284.35,-1031.09 h60
  text ".Print_Date" at 3153.85,-1031.09 h60
  text ".Print_Time" at 3882.85,-1031.09 h60
  text "TEXAS INSTRUMENTS" at 5147.35,-1031.09 h60
M12 Stackup:
  drawing of 295 lines, arcs and shapes, not listed
  text "Layer" at 9855.94,7908.18 h60
  text "Name" at 10265.86,7908.18 h60
  text "Material" at 11195.6,7908.18 h60
  text "Thickness" at 12055.37,7908.18 h60
  text "Constant" at 12705.2,7908.18 h60
  text "Board Layer Stack" at 13275.06,7908.18 h60
  text "Top Overlay" at 10265.86,7788.18 h60
  text "Top Solder" at 10265.86,7668.18 h60
  text "Solder Resist" at 11195.6,7668.18 h60
  text "1.00mil" at 12055.37,7668.18 h60
  text "3.5" at 12705.2,7668.18 h60
  text "1" at 9855.94,7548.18 h60
  text "L01_TOP" at 10265.86,7548.18 h60
  text "0.69mil" at 12055.37,7548.18 h60
  text "Dielectric1" at 10265.86,7428.18 h60
  text "IT-170GTTC" at 11195.6,7428.18 h60
  text "5.48mil" at 12055.37,7428.18 h60
  text "4" at 12705.2,7428.18 h60
  text "2" at 9855.94,7308.18 h60
  text "L02_GND" at 10265.86,7308.18 h60
  text "1.26mil" at 12055.37,7308.18 h60
  text "Dielectric 2" at 10265.86,7188.18 h60
  text "IT-170GTTC" at 11195.6,7188.18 h60
  text "14.64mil" at 12055.37,7188.18 h60
  text "4" at 12705.2,7188.18 h60
  text "3" at 9855.94,7068.18 h60
  text "L03_PWR" at 10265.86,7068.18 h60
  text "1.26mil" at 12055.37,7068.18 h60
  text "Dielectric 3" at 10265.86,6948.18 h60
  text "IT-170GTTC" at 11195.6,6948.18 h60
  text "5.48mil" at 12055.37,6948.18 h60
  text "4" at 12705.2,6948.18 h60
  text "4" at 9855.94,6828.18 h60
  text "L04_BOTTOM" at 10265.86,6828.18 h60
  text "0.69mil" at 12055.37,6828.18 h60
  text "Bottom Solder" at 10265.86,6708.18 h60
  text "Solder Resist" at 11195.6,6708.18 h60
  text "1.00mil" at 12055.37,6708.18 h60
  text "3.5" at 12705.2,6708.18 h60
  text "Bottom Overlay" at 10265.86,6588.18 h60
  text ".Layer_Name" at 611.35,-825.25 h60
M13 Component Bodies Top:
  text ".Layer_Name" at 611.35,-825.25 h60
M14 Component Bodies Bottom:
  text ".Layer_Name" at 611.35,-825.25 h60
M15 Courtyards Top:
  text ".Layer_Name" at 611.35,-825.25 h60
M16 Courtyards Bottom:
  text ".Layer_Name" at 611.35,-825.25 h60
Drill Drawing:
  lines w10: 5370.44,3295.9 5425.69,3295.9 5425.69,3351.15 5370.44,3351.15 5370.44,3295.9
  lines w12: 5320.35,3258.6 8529.41,3258.6 ; 5320.35,3382.92 8529.41,3382.92 ; 5658.21,3134.28 5658.21,3507.24 ; 5990.21,3134.28 5990.21,3507.24 ; 6626.77,3134.28 6626.77,3507.24 ; 6885.91,3134.28 6885.91,3507.24 ; 7261.07,3134.28 7261.07,3507.24 ; 7962.98,3134.28 7962.98,3507.24 ; 5320.35,3134.28 8529.41,3134.28 8529.41,3507.24 5320.35,3507.24 5320.35,3134.28
  text "Symbol" at 5394.94,3420.22 h72
  text "Quantity" at 5695.51,3420.22 h72
  text "Finished Hole Size" at 6027.51,3420.22 h72
  text "Plated" at 6664.07,3420.22 h72
  text "Hole Type" at 6923.21,3420.22 h72
  text "Drill Layer Pair" at 7298.37,3420.22 h72
  text "Hole Tolerance" at 8000.28,3420.22 h72
  text "114" at 5695.51,3295.9 h60
  text "6.00mil (0.152mm)" at 6027.51,3295.9 h60
  text "PTH" at 6664.07,3295.9 h60
  text "Round" at 6923.21,3295.9 h60
  text "L01_TOP - L04_BOTTOM" at 7298.37,3295.9 h60
  text "114 Total" at 5695.51,3171.58 h60
  text ".Layer_Name" at 611.35,-825.25 h60
M17 Embedded Cavity:
  text ".Layer_Name" at 611.35,-825.25 h60
M18 Embedded Assembly:
  text ".Layer_Name" at 611.35,-825.25 h60
M19 Embedded Keepout:
  text ".Layer_Name" at 611.35,-825.25 h60

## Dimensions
34.35,-366.76 to 1034.35,-366.76 on M2 Board Dimensions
